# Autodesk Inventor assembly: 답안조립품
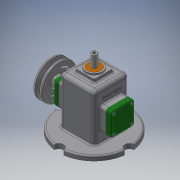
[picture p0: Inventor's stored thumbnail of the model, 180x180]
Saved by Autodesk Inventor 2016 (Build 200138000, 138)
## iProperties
Created: 2018-07
Part Number: 답안조립품
Material: 일반
Document SubType Name: Assembly
Designer: 2-PC07
Author: 2-PC07
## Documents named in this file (16)
- C:\Users\2-PC07\Desktop\480708V1013\답안조립품.iam
- C:\Users\2-PC07\Desktop\480708V1013\본체.ipt
- C:\Users\2-PC07\Desktop\480708V1013\뒤커버.ipt
- C:\Users\2-PC07\Desktop\480708V1013\앞커버.ipt
- C:\Users\2-PC07\Desktop\480708V1013\베어링 12x32x10.ipt
- C:\Users\2-PC07\Desktop\480708V1013\편심축.ipt
- C:\Users\2-PC07\Desktop\480708V1013\오일 실 12 25 7.ipt
- C:\Users\2-PC07\Desktop\480708V1013\키 4x4x10.ipt
- C:\Users\2-PC07\Desktop\480708V1013\V벨트풀리.ipt
- C:\Users\2-PC07\Desktop\480708V1013\링크.ipt
- C:\Users\2-PC07\Desktop\480708V1013\슬라이드.ipt
- C:\Users\2-PC07\Desktop\480708V1013\핀 5x18.ipt
- C:\Users\2-PC07\Desktop\480708V1013\고정핀 1.2x8.ipt
- C:\Users\2-PC07\Desktop\480708V1013\부시.ipt
- C:\Users\2-PC07\Desktop\480708V1013\볼트 M4.ipt
- C:\Users\2-PC07\Desktop\480708V1013\멈춤나사 M3x8.ipt
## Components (3 placed, 3 different names)
1. V벨트풀리:1 — 플러쉬:1
2. 핀 5x18:1
3. 고정핀 1.2x8:1
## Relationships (1: Flush 1)
- 플러쉬:1 [Flush]: V벨트풀리:1
